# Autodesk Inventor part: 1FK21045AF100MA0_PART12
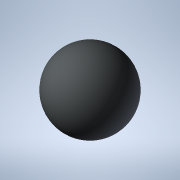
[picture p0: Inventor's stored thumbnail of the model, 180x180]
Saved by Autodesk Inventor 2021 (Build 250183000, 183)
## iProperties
Created: 2025-04
Part Number: 1FK21045AF100MA0_PART12
Material: Generic
Catalog Web Link: www.3dfindit.com
Description: -Servo synchronous motor
Document SubType Name: Modeling
Designer: psAdmin
Mass: 0.137258 g
Surface Area: 1.2868 cm^2
Volume: 0.137258 cm^3
Density: 1 g/cm^3
Appearance: PSOLRGB-212-217-219
Category: PARTsolutions
Title: 1FK21045AF100MA0_PART12
Author: Cadenas PARTsolutions
Comments: Servo synchronous motor
Sending System: PARTsolutions
Preprocessor: ST-DEVELOPER v19.3
PSOL_IDENT_0: {$CADENAS_DATA/23d-libs/siemens_ag/_cat_/52/6b/1fk21045af100ma0.prj},216 {VTYP=3D},{NB=1FK21045AF100
PSOL_IDENT_1: MA0_PART12},{LINA=1FK21045AF100MA0_PART12},{NN=1FK21045AF100MA0_PART12},{NOPRJ=TRUE},{DATE=19.08.202
PSOL_IDENT_2: 5 14:00:38},{GEOMDATE=30.07.2025 02:01:45},{VERSION=},{LINEID=10},{WBVAR=},{WBNUMERIC=}  {NB=1FK2104
PSOL_IDENT_3: 5AF100MA0_PART12},{LINA=1FK21045AF100MA0_PART12},{KT=DUMMY},{PREVIEW=../../../_pool_/cb/72/p_d211_xx
PSOL_IDENT_4: _00434j.png},{DESCSHORT=SIMOTICS S-1FK2 HD, SINAMICS S210 3AC 400V-480V, 2.4 Nm, 3000 rpm},{DESCLONG=
PSOL_IDENT_5: SIMOTICS S-1FK2 HD servo motor M0=2.4 Nm; PN = 0.75 kW at nN=3000 rpm (380-480 V); PN = 0.375 kW at
PSOL_IDENT_6: nN=1500 rpm (200-240 V); with holding brake; degree of protection IP64; cylindrical shaft D19x40mm;
PSOL_IDENT_7: absolute encoder 22-bit + 12-bit multiturn (encoder AM22DQC); with OCC interface; plug size M17, rot
PSOL_IDENT_8: atable; SIMOTICS S-1FK2 servomotorfor a wide range of uses in industrial environments. SIMOTICS S‑1F
PSOL_IDENT_9: K2 servomotors are compact synchronous motors with a high dynamic performance that set themselves ap
PSOL_IDENT_10: art as a result of their high power density, degree of protection and overload capability. The motor
PSOL_IDENT_11: s are available in two variants: as High Dynamic variant (highest dynamic performance as a result of
PSOL_IDENT_12: the low intrinsic moment of inertia for applications demanding a high dynamic performance with low
PSOL_IDENT_13: moved masses) - and as Compact variant (precise and stable closed-loop control for medium up to larg
PSOL_IDENT_14: e moved masses as a result of a medium intrinsic moment of inertia). SIMOTICSS‑1FK2 servomotors full
PSOL_IDENT_15: y exploit their strengths in a system with the SINAMICSS210 frequency converter and simple connectio
PSOL_IDENT_16: n using the one cable connection (OCC). Advantages include the short control and positioning times,
PSOL_IDENT_17: fast and precise correction of disturbing quantities as well as stable control with a high dynamic p
PSOL_IDENT_18: erformance. The servo motors can be configured to address a wide range of requirements. For example
PSOL_IDENT_19: with and without holding brake, IP64 or IP65 degree of protection, singleturn or multiturn absolute
PSOL_IDENT_20: encoders - to name just a few. Further, the servomotors are available in different shaft heights ext
PSOL_IDENT_21: ending from 20 to 100. A shaft sealing ring is available to achieve an IP65 degree of protection and
PSOL_IDENT_22: for subsequent mounting at the motor or as spare part. SIMOTICS - the optimum motor for each and ev
PSOL_IDENT_23: ery motion control application.},{INTNO=804766906411},{SUPPLIERALTNO=1FK2104-5AF10-0MA0},{MANUID=1FK
PSOL_IDENT_24: 21045AF100MA0},{MANUNAME=Siemens},{MANUTYPEDESC=Synchronous motor 1FK2-HD 2.4 NM},{AAU732=SIMOTICS},
PSOL_IDENT_25: {AAO057=S-1FK2},{AAU734=SIMOTICS S-1FK2 HD servo motor M0=2.4 Nm; PN = 0.75 kW at nN=3000 rpm (380-4
PSOL_IDENT_26: 80 V); PN = 0.375 kW at nN=1500 rpm (200-240 V); with holding brake; degree of protection IP64; cyli
PSOL_IDENT_27: ndrical shaft D19x40mm; absolute encoder 22-bit + 12-bit multiturn (encoder AM22DQC); with OCC inter
PSOL_IDENT_28: face; plug size M17, rotatable;},{AAW338=Synchronous motor 1FK2-HD 2.4 NM},{AAO742=SIMOTICS},{AAO663=
PSOL_IDENT_29: 4042948693070},{NOCUPEROU=1},{PRICEQUANTITY=1},{QUANTITYMIN=1},{QUANTITYINT=1},{CTN=85015100},{COO=D
PSOL_IDENT_30: E},{AAO676=1FK2104-5AF10-0MA0},{AAO677=Siemens AG},{ORDERUNIT=C62},{CONTENTUNIT=C62}
NB: 1FK21045AF100MA0_PART12
NT: Servo synchronous motor
NBSYN: $MANUID._PART12
LINA: 1FK21045AF100MA0_PART12
CATALOG: SIEMENS
PREVIEW: ../../../_pool_/cb/72/p_d211_xx_00434j.png
DESCSHORT: SIMOTICS S-1FK2 HD, SINAMICS S210 3AC 400V-480V, 2.4 Nm, 3000 rpm
DESCLONG: SIMOTICS S-1FK2 HD servo motor M0=2.4 Nm; PN = 0.75 kW at nN=3000 rpm (380-480 V); PN = 0.375 kW at nN=1500 rpm (200-240 V); with holding brake; degree of prote
INTNO: 804766906411
SUPPLIERALTNO: 1FK2104-5AF10-0MA0
MANUID: 1FK21045AF100MA0
MANUNAME: Siemens
MANUTYPEDESC: Synchronous motor 1FK2-HD 2.4 NM
AAU732: SIMOTICS
AAO057: S-1FK2
AAU734: SIMOTICS S-1FK2 HD servo motor M0=2.4 Nm; PN = 0.75 kW at nN=3000 rpm (380-480 V); PN = 0.375 kW at nN=1500 rpm (200-240 V); with holding brake; degree of prote
AAW338: Synchronous motor 1FK2-HD 2.4 NM
AAO742: SIMOTICS
AAO663: 4042948693070.0
NOCUPEROU: 1
PRICEQUANTITY: 1
QUANTITYMIN: 1
QUANTITYINT: 1
CTN: 85015100
COO: DE
ARTICLENO: 1FK21045AF100MA0_PART12
BOMINFO: 1FK21045AF100MA0_PART12
CREATOR: CADENAS GmbH
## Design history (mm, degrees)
feature "2025_04_17_15_34_52_0317"
body "Solid1"
